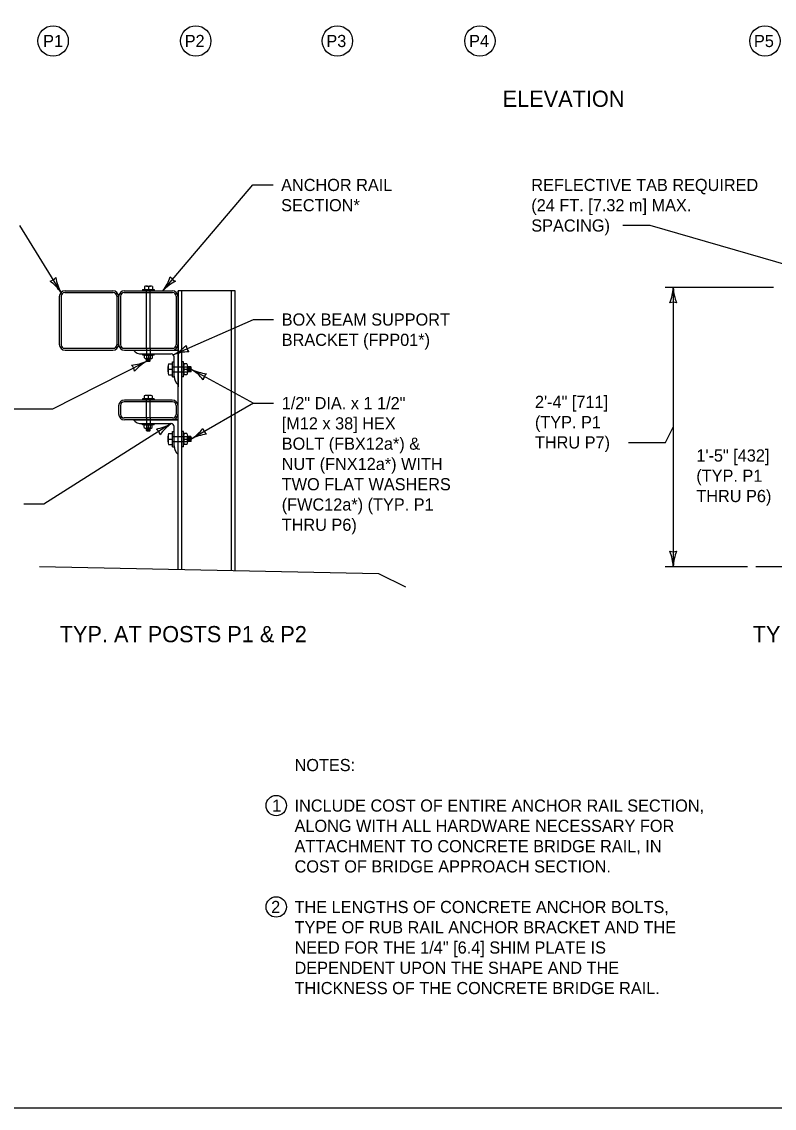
# Model space of a CAD drawing. Extents: x 49983 to 50021, y 49963.5 to 50011.4.
# Drawn here: x 50005.28 to 50008.99, y 49987.8 to 49993.16 of the extents above; entities that cross this region are included whole.
import ezdxf

# ---------------------------------------------------------------- set-up
doc = ezdxf.new("R2010")
doc.units = 0
for name, color, linetype in [('Level 1', 7, 'Continuous'), ('Level 10', 7, 'Continuous'), ('Level 2', 7, 'Continuous'), ('Level 3', 7, 'Continuous')]:
    doc.layers.add(name, color=color, linetype=linetype)

msp = doc.modelspace()

# ---------------------------------------------------------------- linework, layer by layer
at = {"layer": 'Level 1'}
for p, q in [((50005.8802, 49991.8523), (50005.8802, 49991.8375)), ((50005.8901, 49991.8534), (50005.9098, 49991.8534)), ((50005.8999, 49991.8523), (50005.8999, 49991.8375)), ((50005.9197, 49991.8523), (50005.9197, 49991.8375)), ((50005.4607, 49991.8016), (50005.4607, 49991.5674)), ((50005.4698, 49991.8041), (50005.4698, 49991.5648)), ((50005.4874, 49991.8217), (50005.7268, 49991.8217)), ((50005.49, 49991.8309), (50005.7242, 49991.8309)), ((50005.7444, 49991.8041), (50005.7444, 49991.5648)), ((50005.7535, 49991.8016), (50005.7535, 49991.5674)), ((50005.7535, 49991.8016), (50005.7535, 49991.5674)), ((50005.7627, 49991.8041), (50005.7627, 49991.5648)), ((50005.7803, 49991.8217), (50006.0196, 49991.8217)), ((50005.7828, 49991.8309), (50006.017, 49991.8309)), ((50005.8717, 49991.8375), (50005.9278, 49991.8375)), ((50005.8717, 49991.8375), (50005.8717, 49991.8309)), ((50005.8908, 49991.5472), (50005.8908, 49991.8217)), ((50005.9091, 49991.5472), (50005.9091, 49991.8217)), ((50005.9278, 49991.8375), (50005.9278, 49991.8309)), ((50006.0372, 49991.8041), (50006.0372, 49991.5648)), ((50006.0463, 49991.8309), (50006.0463, 49991.5381)), ((50006.0463, 49991.6387), (50006.0463, 49991.8309)), ((50006.3286, 49991.8309), (50006.0463, 49991.8309)), ((50006.0463, 49990.4567), (50006.0463, 49991.8309)), ((50006.0644, 49990.4563), (50006.0644, 49991.8309)), ((50006.3105, 49990.4514), (50006.3105, 49991.8309)), ((50006.3286, 49990.451), (50006.3286, 49991.8309)), ((50006.0463, 49991.7348), (50006.0463, 49991.7348)), ((50005.4874, 49991.5472), (50005.7268, 49991.5472)), ((50005.49, 49991.5381), (50005.7242, 49991.5381)), ((50005.7803, 49991.5472), (50006.0196, 49991.5472)), ((50005.7828, 49991.5381), (50006.0463, 49991.5381)), ((50005.8267, 49991.5381), (50006.0463, 49991.5381)), ((50006.0463, 49991.5381), (50006.0463, 49991.3563)), ((50006.0463, 49991.3672), (50006.0463, 49991.5381)), ((50005.8686, 49991.5191), (50006.0127, 49991.5191)), ((50005.8721, 49991.5125), (50005.8721, 49991.5191)), ((50005.9281, 49991.5125), (50005.8721, 49991.5125)), ((50005.8802, 49991.4996), (50005.8802, 49991.5095)), ((50005.9098, 49991.4965), (50005.8901, 49991.4965)), ((50005.8908, 49991.4857), (50005.8908, 49991.4965)), ((50005.9091, 49991.4857), (50005.8908, 49991.4857)), ((50005.8908, 49991.4857), (50005.8926, 49991.4839)), ((50005.8926, 49991.4839), (50005.9072, 49991.4839)), ((50005.8934, 49991.494), (50005.9063, 49991.494)), ((50005.8934, 49991.4921), (50005.9063, 49991.4921)), ((50005.8934, 49991.4903), (50005.9063, 49991.4903)), ((50005.8934, 49991.4885), (50005.9063, 49991.4885)), ((50005.8999, 49991.5095), (50005.8999, 49991.4996)), ((50005.9091, 49991.4857), (50005.9072, 49991.4839)), ((50005.9091, 49991.4857), (50005.9091, 49991.4965)), ((50005.9197, 49991.4996), (50005.9197, 49991.5095)), ((50005.9281, 49991.5125), (50005.9281, 49991.5191)), ((50005.9987, 49991.47), (50006.0186, 49991.47)), ((50006.0186, 49991.4057), (50006.0186, 49991.4808)), ((50006.0186, 49991.4808), (50006.0274, 49991.4808)), ((50006.0274, 49991.4091), (50006.0274, 49991.5045)), ((50006.0732, 49991.4808), (50006.0644, 49991.4808)), ((50006.0732, 49991.4057), (50006.0732, 49991.4808)), ((50006.0905, 49991.47), (50006.0773, 49991.47)), ((50005.9971, 49991.4303), (50005.9971, 49991.4568)), ((50005.9987, 49991.4435), (50006.0186, 49991.4435)), ((50005.9987, 49991.417), (50006.0186, 49991.417)), ((50006.0773, 49991.4435), (50006.0905, 49991.4435)), ((50006.0905, 49991.417), (50006.0773, 49991.417)), ((50006.0946, 49991.4303), (50006.0946, 49991.4568)), ((50006.1092, 49991.4558), (50006.0946, 49991.4558)), ((50006.1092, 49991.4312), (50006.0946, 49991.4312)), ((50006.0981, 49991.4348), (50006.0981, 49991.4521)), ((50006.1005, 49991.4348), (50006.1005, 49991.4521)), ((50006.103, 49991.4348), (50006.103, 49991.4521)), ((50006.1055, 49991.4348), (50006.1055, 49991.4521)), ((50006.1092, 49991.4558), (50006.1092, 49991.4312)), ((50006.1092, 49991.4558), (50006.1116, 49991.4533)), ((50006.1092, 49991.4312), (50006.1116, 49991.4337)), ((50006.1116, 49991.4337), (50006.1116, 49991.4533)), ((50006.0186, 49991.4057), (50006.0274, 49991.4057)), ((50006.0732, 49991.4057), (50006.0644, 49991.4057)), ((50005.8799, 49991.3135), (50005.8799, 49991.2987)), ((50005.9095, 49991.3147), (50005.8898, 49991.3147)), ((50005.8996, 49991.3135), (50005.8996, 49991.2987)), ((50005.9194, 49991.3135), (50005.9194, 49991.2987)), ((50005.7535, 49991.2628), (50005.7535, 49991.2238)), ((50005.7627, 49991.2654), (50005.7627, 49991.2212)), ((50006.0196, 49991.283), (50005.7803, 49991.283)), ((50006.017, 49991.2921), (50005.7828, 49991.2921)), ((50005.9279, 49991.2987), (50005.8718, 49991.2987)), ((50005.8718, 49991.2987), (50005.8718, 49991.2921)), ((50005.8905, 49991.2036), (50005.8905, 49991.283)), ((50005.9088, 49991.2036), (50005.9088, 49991.283)), ((50005.9279, 49991.2987), (50005.9279, 49991.2921)), ((50006.0372, 49991.2654), (50006.0372, 49991.2212)), ((50006.0196, 49991.2036), (50005.7803, 49991.2036)), ((50006.0463, 49991.1945), (50005.7828, 49991.1945)), ((50005.8267, 49991.1945), (50006.0463, 49991.1945)), ((50005.8686, 49991.1755), (50006.0127, 49991.1755)), ((50005.8718, 49991.169), (50005.8718, 49991.1755)), ((50005.9279, 49991.169), (50005.8718, 49991.169)), ((50005.8799, 49991.156), (50005.8799, 49991.1659)), ((50005.9095, 49991.153), (50005.8898, 49991.153)), ((50005.8905, 49991.1421), (50005.8905, 49991.153)), ((50005.8931, 49991.1504), (50005.906, 49991.1504)), ((50005.8931, 49991.1486), (50005.906, 49991.1486)), ((50005.8996, 49991.1659), (50005.8996, 49991.156)), ((50005.9088, 49991.1421), (50005.9088, 49991.153)), ((50005.9194, 49991.156), (50005.9194, 49991.1659)), ((50005.9279, 49991.169), (50005.9279, 49991.1755)), ((50006.0274, 49991.0655), (50006.0274, 49991.1609)), ((50005.9088, 49991.1421), (50005.8905, 49991.1421)), ((50005.8905, 49991.1421), (50005.8923, 49991.1403)), ((50005.8923, 49991.1403), (50005.907, 49991.1403)), ((50005.8931, 49991.1467), (50005.906, 49991.1467)), ((50005.8931, 49991.1449), (50005.906, 49991.1449)), ((50005.9088, 49991.1421), (50005.907, 49991.1403)), ((50005.9971, 49991.0865), (50005.9971, 49991.113)), ((50005.9987, 49991.1263), (50006.0186, 49991.1263)), ((50005.9987, 49991.0998), (50006.0186, 49991.0998)), ((50006.0186, 49991.0619), (50006.0186, 49991.1371)), ((50006.0186, 49991.1371), (50006.0274, 49991.1371)), ((50006.0732, 49991.1371), (50006.0644, 49991.1371)), ((50006.0732, 49991.0619), (50006.0732, 49991.1371)), ((50006.0905, 49991.1263), (50006.0773, 49991.1263)), ((50006.0773, 49991.0998), (50006.0905, 49991.0998)), ((50006.0946, 49991.0865), (50006.0946, 49991.113)), ((50006.1092, 49991.1121), (50006.0946, 49991.1121)), ((50006.0981, 49991.0911), (50006.0981, 49991.1083)), ((50006.1005, 49991.0911), (50006.1005, 49991.1083)), ((50006.103, 49991.0911), (50006.103, 49991.1083)), ((50006.1055, 49991.0911), (50006.1055, 49991.1083)), ((50006.1092, 49991.1121), (50006.1092, 49991.0875)), ((50006.1092, 49991.1121), (50006.1116, 49991.1096)), ((50006.1116, 49991.09), (50006.1116, 49991.1096)), ((50005.9987, 49991.0733), (50006.0186, 49991.0733)), ((50006.0186, 49991.0619), (50006.0274, 49991.0619)), ((50006.0732, 49991.0619), (50006.0644, 49991.0619)), ((50006.0905, 49991.0733), (50006.0773, 49991.0733)), ((50006.1092, 49991.0875), (50006.0946, 49991.0875)), ((50006.1092, 49991.0875), (50006.1116, 49991.09)), ((50005.3631, 49990.4704), (50007.0341, 49990.4369)), ((50008.8949, 49990.4704), (50010.5661, 49990.4704)), ((50007.0341, 49990.4369), (50007.1681, 49990.3699))]:
    msp.add_line(p, q, dxfattribs=at)
msp.add_lwpolyline([(49999.3835, 49998.9992), (50016.7501, 49998.9992), (50016.7501, 49987.7988), (49999.3835, 49987.7988)], close=True, dxfattribs=at)
for centre, radius, start, end in [((50005.8901, 49991.812), 0.0415, 76.2307, 103.7693), ((50005.9098, 49991.812), 0.0415, 76.2307, 103.7693), ((50005.49, 49991.8016), 0.0293, 90, 180), ((50005.4874, 49991.8041), 0.0176, 90, 180), ((50005.7242, 49991.8016), 0.0293, 0, 90), ((50005.7268, 49991.8041), 0.0176, 0, 90), ((50005.7828, 49991.8016), 0.0293, 90, 180), ((50005.7803, 49991.8041), 0.0176, 90, 180), ((50006.017, 49991.8016), 0.0293, 0, 90), ((50006.0196, 49991.8041), 0.0176, 0, 90), ((50005.49, 49991.5674), 0.0293, 180, 270), ((50005.4874, 49991.5648), 0.0176, 180, 270), ((50005.7242, 49991.5674), 0.0293, 270, 0), ((50005.7268, 49991.5648), 0.0176, 270, 0), ((50005.7828, 49991.5674), 0.0293, 180, 270), ((50005.7803, 49991.5648), 0.0176, 180, 270), ((50005.8668, 49991.5709), 0.0518, 219.3297, 271.9596), ((50006.017, 49991.5674), 0.0293, 270, 0), ((50006.0196, 49991.5648), 0.0176, 270, 0), ((50005.8901, 49991.495), 0.0175, 55.616, 124.384), ((50005.8901, 49991.514), 0.0175, 235.616, 304.384), ((50005.9098, 49991.495), 0.0175, 55.616, 124.384), ((50005.9098, 49991.514), 0.0175, 235.616, 304.384), ((50006.0528, 49991.4568), 0.0557, 166.2307, 193.7693), ((50006.0127, 49991.5045), 0.0146, 0, 90), ((50006.0967, 49991.4568), 0.0235, 145.616, 214.384), ((50006.0712, 49991.4568), 0.0235, 325.616, 34.384), ((50006.0528, 49991.4303), 0.0557, 166.2307, 193.7693), ((50006.0967, 49991.4303), 0.0235, 145.616, 214.384), ((50006.0712, 49991.4303), 0.0235, 325.616, 34.384), ((50006.0792, 49991.4073), 0.0518, 178.0404, 230.6703), ((50005.8898, 49991.2732), 0.0415, 76.2307, 103.7693), ((50005.9095, 49991.2732), 0.0415, 76.2307, 103.7693), ((50005.7828, 49991.2628), 0.0293, 90, 180), ((50005.7803, 49991.2654), 0.0176, 90, 180), ((50006.017, 49991.2628), 0.0293, 0, 90), ((50006.0196, 49991.2654), 0.0176, 0, 90), ((50005.7828, 49991.2238), 0.0293, 180, 270), ((50005.7803, 49991.2212), 0.0176, 180, 270), ((50006.017, 49991.2238), 0.0293, 270, 0), ((50006.0196, 49991.2212), 0.0176, 270, 0), ((50005.8668, 49991.2273), 0.0518, 219.3297, 271.9596), ((50005.8898, 49991.1515), 0.0175, 55.616, 124.384), ((50005.8898, 49991.1705), 0.0175, 235.616, 304.384), ((50005.9095, 49991.1515), 0.0175, 55.616, 124.384), ((50005.9095, 49991.1705), 0.0175, 235.616, 304.384), ((50006.0127, 49991.1609), 0.0146, 0, 90), ((50006.0528, 49991.113), 0.0557, 166.2307, 193.7693), ((50006.0528, 49991.0865), 0.0557, 166.2307, 193.7693), ((50006.0967, 49991.113), 0.0235, 145.616, 214.384), ((50006.0967, 49991.0865), 0.0235, 145.616, 214.384), ((50006.0712, 49991.113), 0.0235, 325.616, 34.384), ((50006.0712, 49991.0865), 0.0235, 325.616, 34.384), ((50006.0792, 49991.0638), 0.0518, 178.0404, 230.6703)]:
    msp.add_arc(centre, radius, start, end, dxfattribs=at)
at = {"layer": 'Level 10'}
for p, q in [((50005.8908, 49991.8217), (50005.8908, 49991.8375)), ((50005.9091, 49991.8217), (50005.9091, 49991.8375)), ((50005.8908, 49991.5472), (50005.8908, 49991.4965)), ((50005.9091, 49991.5472), (50005.9091, 49991.4965)), ((50006.0186, 49991.4558), (50006.0946, 49991.4558)), ((50006.0186, 49991.4312), (50006.0946, 49991.4312)), ((50005.8905, 49991.283), (50005.8905, 49991.2987)), ((50005.9088, 49991.283), (50005.9088, 49991.2987)), ((50005.8905, 49991.2036), (50005.8905, 49991.153)), ((50005.9088, 49991.2036), (50005.9088, 49991.153)), ((50006.0186, 49991.1121), (50006.0946, 49991.1121)), ((50006.0186, 49991.0875), (50006.0946, 49991.0875))]:
    msp.add_line(p, q, dxfattribs=at)
at = {"layer": 'Level 2'}
for centre, radius in [((50005.4303, 49993.0629), 0.075), ((50006.1337, 49993.0629), 0.075), ((50006.8321, 49993.0629), 0.075), ((50007.5349, 49993.0629), 0.075), ((50008.9404, 49993.0629), 0.075), ((50006.5306, 49989.2917), 0.0503), ((50006.5306, 49988.7917), 0.0503)]:
    msp.add_circle(centre, radius, dxfattribs=at)
at = {"layer": 'Level 3'}
for p, q in [((50005.9718, 49991.8309), (50006.4147, 49992.3529)), ((50006.4147, 49992.3529), (50006.5147, 49992.3529)), ((50005.4693, 49991.8223), (50005.266, 49992.1531)), ((50008.3742, 49992.1529), (50008.2392, 49992.1529)), ((50009.0687, 49991.952), (50008.3742, 49992.1529)), ((50008.9819, 49991.8474), (50008.4483, 49991.8474)), ((50008.4883, 49991.8474), (50008.4883, 49990.4704)), ((50006.0231, 49991.5148), (50006.4177, 49991.6892)), ((50006.4177, 49991.6892), (50006.5177, 49991.6892)), ((50006.1116, 49991.4435), (50006.4177, 49991.2769)), ((50006.4177, 49991.2769), (50006.1116, 49991.0998)), ((50006.4177, 49991.2769), (50006.5177, 49991.2769)), ((50008.4497, 49991.083), (50008.4883, 49991.1589)), ((50008.2683, 49991.083), (50008.4497, 49991.083)), ((50008.4483, 49990.4704), (50008.8549, 49990.4704))]:
    msp.add_line(p, q, dxfattribs=at)
for points in [[(50004.7931, 49991.2484), (50005.4283, 49991.2484), (50005.8926, 49991.4839)], [(50006.0128, 49991.1755), (50005.3851, 49990.7781), (50005.2851, 49990.7781)]]:
    msp.add_lwpolyline(points, dxfattribs=at)
for centre, radius, start, end in [((50005.7869, 49991.9727), 0.233, 322.5167, 341.7665), ((50006.0548, 49991.9286), 0.0548, 211.8282, 247.5505), ((50005.4022, 49991.9315), 0.0548, 283.7046, 319.427), ((50005.277, 49991.6907), 0.233, 34.3931, 53.643), ((50005.6633, 49991.9308), 0.2223, 189.0218, 209.2053), ((50006.1353, 49991.6802), 0.2223, 117.1454, 137.3289), ((50008.2661, 49991.8565), 0.2223, 337.456, 357.6395), ((50008.721, 49991.8589), 0.233, 182.8273, 202.0772), ((50008.4883, 49991.7191), 0.0548, 72.1388, 107.8612), ((50005.9185, 49991.723), 0.233, 296.6642, 315.914), ((50006.1045, 49991.3079), 0.2223, 91.2929, 111.4764), ((50006.1404, 49991.5666), 0.0548, 185.9757, 221.698), ((50005.8003, 49991.6861), 0.2223, 274.345, 294.5285), ((50005.8003, 49991.6861), 0.2223, 274.345, 294.5285), ((50006.0081, 49991.2815), 0.233, 119.7163, 138.9661), ((50006.0081, 49991.2815), 0.233, 119.7163, 138.9661), ((50005.7783, 49991.4259), 0.0548, 9.0278, 44.7501), ((50005.7783, 49991.4259), 0.0548, 9.0278, 44.7501), ((50005.9974, 49991.2528), 0.2223, 38.8919, 59.0754), ((50006.2128, 49991.6534), 0.233, 244.2632, 263.5131), ((50006.2243, 49991.3822), 0.0548, 133.5747, 169.2971), ((50005.9017, 49991.3681), 0.2223, 279.7939, 299.9774), ((50005.9045, 49991.107), 0.0548, 14.4767, 50.1991), ((50006.147, 49990.9851), 0.233, 125.1652, 144.415), ((50005.9851, 49991.2954), 0.233, 302.885, 322.1348), ((50006.2226, 49991.164), 0.0548, 192.1965, 227.9188), ((50006.215, 49990.9029), 0.2223, 97.5137, 117.6972), ((50008.4883, 49990.5986), 0.0548, 252.1388, 287.8612), ((50008.2555, 49990.4589), 0.233, 2.8273, 22.0772), ((50008.7104, 49990.4612), 0.2223, 157.456, 177.6395)]:
    msp.add_arc(centre, radius, start, end, dxfattribs=at)

# ---------------------------------------------------------------- texts
at = {"layer": 'Level 2'}
for s, height, p in [('P1', 0.06, (50005.3811, 49993.0329)), ('P2', 0.06, (50006.0793, 49993.033)), ('P3', 0.06, (50006.7777, 49993.033)), ('P4', 0.06, (50007.4817, 49993.033)), ('P5', 0.06, (50008.8863, 49993.033)), ('ELEVATION', 0.08, (50007.6472, 49992.7381)), ('ANCHOR RAIL', 0.06, (50006.5547, 49992.3229)), ('REFLECTIVE TAB REQUIRED', 0.06, (50007.7883, 49992.3229)), ('SECTION*', 0.06, (50006.5547, 49992.2229)), ('(24 FT. [7.32 m] MAX. ', 0.06, (50007.7883, 49992.2229)), ('SPACING)', 0.06, (50007.7883, 49992.1229)), ('BOX BEAM SUPPORT', 0.06, (50006.5577, 49991.6592)), ('BRACKET (FPP01*)', 0.06, (50006.5577, 49991.5592)), ('1/2" DIA. x 1 1/2"', 0.06, (50006.5577, 49991.2469)), ('2\'-4" [711]', 0.06, (50007.8063, 49991.253)), ('[M12 x 38] HEX', 0.06, (50006.5577, 49991.1469)), ('(TYP. P1', 0.06, (50007.8063, 49991.153)), ('BOLT (FBX12a*) &', 0.06, (50006.5577, 49991.0469)), ('THRU P7)', 0.06, (50007.8063, 49991.053)), ('1\'-5" [432]', 0.06, (50008.6021, 49990.9886)), ('NUT (FNX12a*) WITH', 0.06, (50006.5577, 49990.9469)), ('(TYP. P1', 0.06, (50008.6021, 49990.8886)), ('TWO FLAT WASHERS', 0.06, (50006.5577, 49990.8469)), ('THRU P6)', 0.06, (50008.6021, 49990.7886)), ('(FWC12a*) (TYP. P1', 0.06, (50006.5577, 49990.7469)), ('THRU P6)', 0.06, (50006.5577, 49990.6469)), ('TYP. AT POSTS P1 & P2', 0.08, (50005.4629, 49990.0973)), ('TYP. AT POSTS P3 THRU P5', 0.08, (50008.8801, 49990.0973)), ('NOTES:', 0.06, (50006.6209, 49989.4617)), ('1', 0.06, (50006.5109, 49989.2617)), ('INCLUDE COST OF ENTIRE ANCHOR RAIL SECTION, ', 0.06, (50006.6209, 49989.2617)), ('ALONG WITH ALL HARDWARE NECESSARY FOR ', 0.06, (50006.6209, 49989.1617)), ('ATTACHMENT TO CONCRETE BRIDGE RAIL, IN ', 0.06, (50006.6209, 49989.0617)), ('COST OF BRIDGE APPROACH SECTION.', 0.06, (50006.6209, 49988.9617)), ('2', 0.06, (50006.5055, 49988.7617)), ('THE LENGTHS OF CONCRETE ANCHOR BOLTS,', 0.06, (50006.6209, 49988.7617)), ('TYPE OF RUB RAIL ANCHOR BRACKET AND THE', 0.06, (50006.6209, 49988.6617)), ('NEED FOR THE 1/4" [6.4] SHIM PLATE IS ', 0.06, (50006.6209, 49988.5617)), ('DEPENDENT UPON THE SHAPE AND THE ', 0.06, (50006.6209, 49988.4617)), ('THICKNESS OF THE CONCRETE BRIDGE RAIL.', 0.06, (50006.6209, 49988.3617))]:
    msp.add_text(s, height=height, dxfattribs=at).set_placement(p)

doc.saveas('drawing.dxf')
